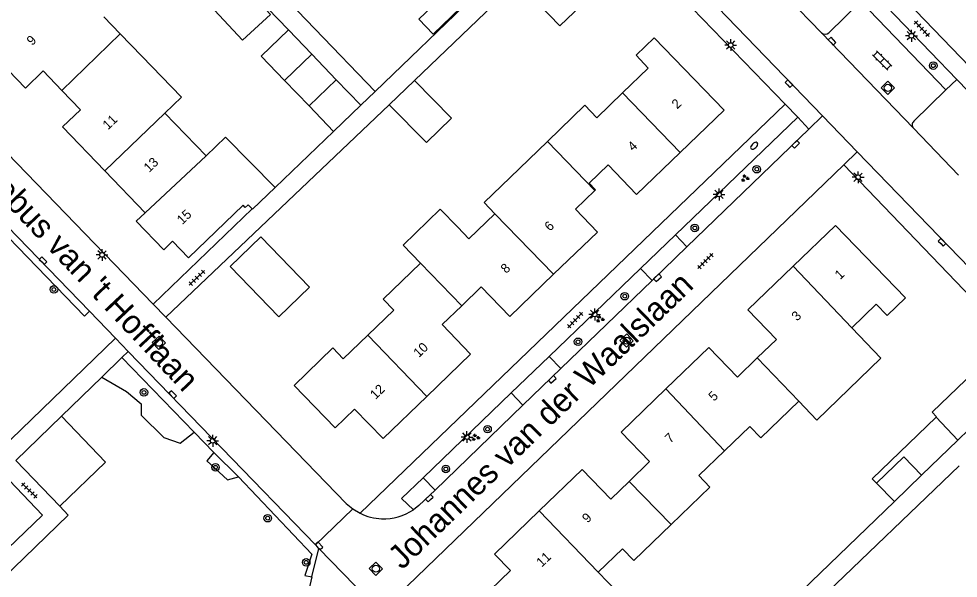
# Model space of a CAD drawing. Extents: x 137999 to 141000, y 397500 to 400501.
# Drawn here: x 138533.8 to 138633.1, y 399346.9 to 399406.1 of the extents above; entities that cross this region are included whole.
import ezdxf

# ---------------------------------------------------------------- set-up
doc = ezdxf.new("R2010")
doc.units = 0
for name, color, linetype in [('gg-afsc-erfafscheiding', 7, 'Continuous'), ('gg-anno-huisnummerreeks BGT', 7, 'Continuous'), ('gg-anno-openbare ruimte label', 7, 'Continuous'), ('gg-bbg-bijgebouw', 7, 'Continuous'), ('gg-bbg-gedigitaliseerde bebouwing', 7, 'Continuous'), ('gg-bbg-gedigitaliseerde bijgebouw', 7, 'Continuous'), ('gg-bbg-hoofdgebouw', 7, 'Continuous'), ('gg-bbg-luifel en loopbrug', 7, 'Continuous'), ('gg-bbg-tussenscheiding', 7, 'Continuous'), ('gg-knt-verharding', 7, 'Continuous'), ('gg-knt-verharding nz', 7, 'Continuous'), ('gt-grn-groengrens', 7, 'Continuous'), ('gt-grn-weggrens', 7, 'Continuous'), ('gt-symb-boom', 7, 'Continuous'), ('gt-symb-brandkraan', 7, 'Continuous'), ('gt-symb-groenvak', 7, 'Continuous'), ('gt-symb-klinker verharding', 7, 'Continuous'), ('gt-symb-kolk', 7, 'Continuous'), ('gt-symb-lichtmast', 7, 'Continuous'), ('gt-symb-rioolschacht', 7, 'Continuous'), ('gt-symb-tegel verharding', 7, 'Continuous')]:
    doc.layers.add(name, color=color, linetype=linetype)

# ---------------------------------------------------------------- blocks, each defined once
blk = doc.blocks.new('gt0-BOOM')
at = {"layer": 'gt-symb-boom'}
for radius in [0.4, 0.2]:
    blk.add_circle((0, 0), radius, dxfattribs=at)
blk = doc.blocks.new('gt0-KOLK')
at = {"layer": 'gt-symb-kolk'}
blk.add_lwpolyline([(0, 0), (0.375, 0), (0.375, 0.4), (-0.375, 0.4), (-0.375, 0), (0, 0)], dxfattribs=at)
blk = doc.blocks.new('gt0-LMAST')
at = {"layer": 'gt-symb-lichtmast'}
for p, q in [((-0.182, 0.173), (-0.447, 0.438)), ((-0.005, 0.246), (-0.005, 0.621)), ((0.172, 0.173), (0.437, 0.438)), ((-0.255, -0.004), (-0.63, -0.004)), ((-0.182, -0.181), (-0.447, -0.446)), ((-0.005, -0.254), (-0.005, -0.629)), ((0.437, -0.446), (0.172, -0.181)), ((0.245, -0.004), (0.62, -0.004))]:
    blk.add_line(p, q, dxfattribs=at)
blk.add_circle((-0.005, -0.004), 0.25, dxfattribs=at)
blk = doc.blocks.new('gt0-RS')
at = {"layer": 'gt-symb-rioolschacht'}
blk.add_lwpolyline([(-0.5, -0.5), (0.5, -0.5), (0.5, 0.5), (-0.5, 0.5)], close=True, dxfattribs=at)
blk.add_circle((0, 0), 0.375, dxfattribs=at)
blk = doc.blocks.new('gt0-TEG1')
at = {"layer": 'gt-symb-tegel verharding'}
for p, q in [((-1.125, 0), (1.125, 0)), ((-0.9, -0.25), (-0.9, 0.25)), ((-0.45, -0.25), (-0.45, 0.25)), ((0, -0.25), (0, 0.25)), ((0.45, -0.25), (0.45, 0.25)), ((0.9, -0.25), (0.9, 0.25))]:
    blk.add_line(p, q, dxfattribs=at)
blk = doc.blocks.new('gt0-KL1')
at = {"layer": 'gt-symb-klinker verharding'}
for p, q in [((-1.15, 0.3), (1.15, 0.3)), ((-1, -0.3), (-1, 0.3)), ((-0.5, 0.3), (-0.5, 0.45)), ((0, -0.3), (0, 0.3)), ((0.5, 0.3), (0.5, 0.45)), ((1, -0.3), (1, 0.3)), ((-1.15, -0.3), (1.15, -0.3)), ((-0.5, -0.45), (-0.5, -0.3)), ((0.5, -0.45), (0.5, -0.3))]:
    blk.add_line(p, q, dxfattribs=at)
blk = doc.blocks.new('gt0-GRVAK')
at = {"layer": 'gt-symb-groenvak'}
for p, q in [((-0.11, 0.189), (-0.228, 0.24)), ((-0.182, 0.153), (0.088, 0.153)), ((-0.091, 0.211), (-0.156, 0.322)), ((-0.047, 0.214), (-0.047, 0.393)), ((-0.004, 0.211), (0.061, 0.322)), ((0.015, 0.189), (0.133, 0.24)), ((0.262, -0.052), (0.197, 0.059)), ((0.305, -0.049), (0.305, 0.13)), ((0.349, -0.052), (0.414, 0.059)), ((-0.245, -0.228), (-0.363, -0.177)), ((-0.318, -0.264), (-0.047, -0.264)), ((-0.226, -0.206), (-0.291, -0.095)), ((-0.183, -0.203), (-0.183, -0.024)), ((-0.139, -0.206), (-0.074, -0.095)), ((-0.12, -0.228), (-0.002, -0.177)), ((0.243, -0.074), (0.125, -0.023)), ((0.17, -0.11), (0.441, -0.11)), ((0.368, -0.074), (0.486, -0.023))]:
    blk.add_line(p, q, dxfattribs=at)
blk = doc.blocks.new('gt0-BR')
at = {"layer": 'gt-symb-brandkraan'}
for centre, radius, start, end in [((-0.244, 0), 0.206, 107.56694, 252.43307), ((0.599, -2.664), 3, 106.89205, 107.56694), ((0, -0.691), 0.938, 73.10799, 106.89205), ((-0.599, -2.664), 3, 72.43309, 73.10799), ((0.244, 0), 0.206, 287.56695, 72.43309), ((0.599, 2.664), 3, 252.43307, 253.10797), ((0, 0.691), 0.938, 253.10797, 286.89206), ((-0.599, 2.664), 3, 286.89206, 287.56695)]:
    blk.add_arc(centre, radius, start, end, dxfattribs=at)

msp = doc.modelspace()

# ---------------------------------------------------------------- linework, layer by layer
at = {"layer": 'gg-afsc-erfafscheiding'}
for p, q in [((138562.298, 399404.947), (138532.585, 399435.849)), ((138586.503, 399410.042), (138575.628, 399399.609)), ((138571.465, 399398.456), (138569.945, 399396.994)), ((138572.963, 399397.042), (138549.319, 399374.578)), ((138560.882, 399388.271), (138567.063, 399394.22)), ((138615.788, 399342.104), (138633.204, 399358.84)), ((138594.27, 399324.093), (138626.367, 399355.056))]:
    msp.add_line(p, q, dxfattribs=at)
msp.add_lwpolyline([(138571.465, 399398.456), (138526.794, 399444.89), (138537.203, 399454.925)], dxfattribs=at)
at = {"layer": 'gg-bbg-bijgebouw'}
for p, q in [((138637.561, 399365.896), (138633.07, 399361.547)), ((138629.241, 399357.839), (138626.367, 399355.056))]:
    msp.add_line(p, q, dxfattribs=at)
msp.add_lwpolyline([(138586.503, 399410.042), (138591, 399405.377), (138596.246, 399410.424), (138591.726, 399415.077)], dxfattribs=at)
at = {"layer": 'gg-bbg-gedigitaliseerde bebouwing'}
for p, q in [((138542.792, 399406.337), (138544.514, 399404.551)), ((138546.806, 399402.175), (138544.514, 399404.551)), ((138549.245, 399396.149), (138553.598, 399391.637)), ((138589.692, 399393.158), (138585.75, 399389.352)), ((138597.104, 399345.478), (138595.056, 399347.598))]:
    msp.add_line(p, q, dxfattribs=at)
for points in [[(138546.806, 399402.175), (138550.993, 399397.835), (138549.245, 399396.149)], [(138599.05, 399402.27), (138600.34, 399400.902), (138597.634, 399398.289)], [(138597.634, 399398.289), (138594.918, 399395.667), (138593.651, 399396.979), (138589.692, 399393.158)], [(138553.598, 399391.637), (138555.65, 399393.597), (138560.882, 399388.271)], [(138585.75, 399389.352), (138582.988, 399386.686), (138584.132, 399385.501)], [(138580.197, 399384.087), (138578.349, 399385.998), (138574.413, 399382.191), (138576.258, 399380.284)], [(138584.132, 399385.501), (138581.389, 399382.852), (138580.197, 399384.087)], [(138576.258, 399380.284), (138572.312, 399376.475), (138573.441, 399375.305), (138570.686, 399372.645)], [(138625.6, 399374.73), (138624.454, 399375.921), (138621.853, 399373.418)], [(138621.853, 399373.418), (138624.948, 399370.222), (138618.177, 399363.665), (138616.248, 399365.657)], [(138570.686, 399372.645), (138568.101, 399370.15), (138566.989, 399371.302), (138562.89, 399367.34)], [(138616.248, 399365.657), (138612.248, 399361.808), (138611.093, 399363.007), (138608.42, 399360.434)], [(138608.42, 399360.434), (138605.678, 399357.796), (138606.855, 399356.572), (138602.757, 399352.629)], [(138602.757, 399352.629), (138598.802, 399348.823), (138597.613, 399350.059), (138595.056, 399347.598)]]:
    msp.add_lwpolyline(points, dxfattribs=at)
at = {"layer": 'gg-bbg-gedigitaliseerde bijgebouw'}
for p, q in [((138562.298, 399404.947), (138564.768, 399402.379)), ((138564.768, 399402.379), (138567.357, 399399.687)), ((138564.473, 399396.912), (138561.882, 399399.603)), ((138564.473, 399396.912), (138567.357, 399399.687)), ((138575.628, 399399.609), (138572.963, 399397.042)), ((138633.07, 399361.547), (138630.772, 399363.98)), ((138624.49, 399356.997), (138626.367, 399355.056))]:
    msp.add_line(p, q, dxfattribs=at)
for points in [[(138577.609, 399404.512), (138576.077, 399406.101), (138578.996, 399408.916), (138580.528, 399407.326), (138577.609, 399404.512)], [(138561.882, 399399.603), (138559.412, 399402.169), (138562.298, 399404.947)], [(138572.963, 399397.042), (138576.883, 399393.042), (138579.526, 399395.632), (138575.628, 399399.609)], [(138556.144, 399379.926), (138559.376, 399383.052), (138564.522, 399377.732), (138561.29, 399374.606), (138556.144, 399379.926)], [(138634.808, 399368.789), (138630.372, 399364.5), (138630.825, 399364.031), (138630.772, 399363.98)], [(138629.241, 399357.839), (138627.362, 399359.778), (138624.49, 399356.997)]]:
    msp.add_lwpolyline(points, dxfattribs=at)
at = {"layer": 'gg-bbg-hoofdgebouw'}
for p, q in [((138599.1, 399387.54), (138603.719, 399391.984)), ((138542.874, 399390.051), (138547.142, 399385.616)), ((138551.73, 399380.85), (138557.497, 399386.4)), ((138558.046, 399386.458), (138558.465, 399386.023)), ((138590.327, 399379.097), (138594.96, 399383.57)), ((138550.051, 399382.595), (138551.73, 399380.85)), ((138585.763, 399347.766), (138579.681, 399341.886))]:
    msp.add_line(p, q, dxfattribs=at)
for points in [[(138603.719, 399391.984), (138608.36, 399396.45), (138600.98, 399404.13), (138599.05, 399402.27)], [(138529.99, 399403.445), (138534.48, 399398.79), (138536.37, 399400.62), (138538.344, 399398.555)], [(138542.874, 399390.051), (138538.4, 399394.7), (138540.3, 399396.51), (138538.344, 399398.555)], [(138599.1, 399387.54), (138596.093, 399390.676), (138594.092, 399388.757), (138594.778, 399388.041), (138594.707, 399387.973)], [(138560.882, 399388.271), (138558.504, 399385.983), (138558.465, 399386.023)], [(138594.707, 399387.973), (138592.639, 399385.99), (138594.96, 399383.57)], [(138558.046, 399386.458), (138557.732, 399386.156), (138557.497, 399386.4)], [(138547.142, 399385.616), (138546.21, 399384.719), (138549.113, 399381.692), (138550.051, 399382.595)], [(138615.679, 399379.953), (138620.15, 399384.26), (138627.54, 399376.61), (138625.6, 399374.73)], [(138611.871, 399370.25), (138613.89, 399372.2), (138610.88, 399375.33), (138615.679, 399379.953)], [(138580.628, 399375.777), (138582.69, 399377.76), (138585.7, 399374.63), (138590.327, 399379.097)], [(138576.933, 399366.183), (138581.56, 399370.65), (138578.55, 399373.78), (138580.628, 399375.777)], [(138602.219, 399366.97), (138606.76, 399371.34), (138609.77, 399368.22), (138611.871, 399370.25)], [(138562.89, 399367.34), (138567.23, 399362.85), (138569.28, 399364.83), (138572.3, 399361.71), (138576.933, 399366.183)], [(138598.31, 399357.179), (138600.49, 399359.28), (138597.48, 399362.41), (138602.219, 399366.97)], [(138588.821, 399354.058), (138593.37, 399358.44), (138596.38, 399355.32), (138598.31, 399357.179)], [(138585.763, 399347.766), (138584.09, 399349.5), (138588.821, 399354.058)]]:
    msp.add_lwpolyline(points, dxfattribs=at)
at = {"layer": 'gg-bbg-luifel en loopbrug'}
for p, q in [((138567.357, 399399.687), (138569.945, 399396.994)), ((138569.945, 399396.994), (138567.063, 399394.22)), ((138567.063, 399394.22), (138564.473, 399396.912)), ((138633.07, 399361.547), (138629.241, 399357.839))]:
    msp.add_line(p, q, dxfattribs=at)
for points in [[(138551.263, 399411.068), (138551, 399410.825), (138557.446, 399403.854), (138560.406, 399406.592), (138555.684, 399411.699)], [(138630.772, 399363.98), (138624.036, 399357.467), (138624.49, 399356.997)]]:
    msp.add_lwpolyline(points, dxfattribs=at)
at = {"layer": 'gg-bbg-tussenscheiding'}
for p, q in [((138544.514, 399404.551), (138538.344, 399398.555)), ((138564.768, 399402.379), (138561.882, 399399.603)), ((138603.719, 399391.984), (138597.634, 399398.289)), ((138549.245, 399396.149), (138542.874, 399390.051)), ((138594.707, 399387.973), (138589.692, 399393.158)), ((138547.142, 399385.616), (138553.598, 399391.637)), ((138590.327, 399379.097), (138584.132, 399385.501)), ((138580.628, 399375.777), (138576.258, 399380.284)), ((138615.679, 399379.953), (138621.853, 399373.418)), ((138576.933, 399366.183), (138570.686, 399372.645)), ((138616.248, 399365.657), (138611.871, 399370.25)), ((138602.219, 399366.97), (138608.42, 399360.434)), ((138602.757, 399352.629), (138598.31, 399357.179)), ((138588.821, 399354.058), (138595.056, 399347.598))]:
    msp.add_line(p, q, dxfattribs=at)
at = {"layer": 'gg-knt-verharding'}
for p, q in [((138531.226, 399486.574), (138618.77, 399395.87)), ((138503.24, 399422.202), (138548.006, 399375.941)), ((138571.465, 399398.456), (138593.253, 399419.425)), ((138614.83, 399397.11), (138594.734, 399417.888)), ((138614.467, 399408.99), (138618.663, 399404.64)), ((138632.984, 399399.715), (138623.96, 399409.087)), ((138622.835, 399407.952), (138619.421, 399404.661)), ((138622.835, 399407.952), (138631.824, 399398.61)), ((138618.663, 399404.64), (138628.387, 399394.556)), ((138631.824, 399398.61), (138632.984, 399399.715)), ((138631.824, 399398.61), (138628.419, 399395.285)), ((138569.886, 399353.814), (138614.83, 399397.11)), ((138603.222, 399383.256), (138616.144, 399395.708)), ((138616.144, 399395.708), (138617.323, 399394.471)), ((138618.77, 399395.87), (138617.323, 399394.471)), ((138622.45, 399392.05), (138618.77, 399395.87)), ((138522.628, 399394.451), (138541.267, 399375.185)), ((138617.323, 399394.471), (138604.417, 399381.999)), ((138628.387, 399394.556), (138633.164, 399389.603)), ((138622.45, 399392.05), (138621.021, 399390.671)), ((138622.45, 399392.05), (138662.293, 399350.768)), ((138573.864, 399345.159), (138621.021, 399390.671)), ((138641.4, 399369.436), (138621.021, 399390.671)), ((138558.465, 399386.023), (138548.006, 399375.941)), ((138604.417, 399381.999), (138603.222, 399383.256)), ((138604.417, 399381.999), (138600.746, 399378.451)), ((138589.875, 399370.406), (138599.513, 399379.722)), ((138599.513, 399379.722), (138600.746, 399378.451)), ((138600.746, 399378.451), (138591.089, 399369.117)), ((138541.267, 399375.185), (138544.013, 399372.347)), ((138544.691, 399370.291), (138542.556, 399368.225)), ((138545.367, 399370.946), (138544.691, 399370.291)), ((138545.367, 399370.946), (138565.165, 399350.46)), ((138591.089, 399369.117), (138589.875, 399370.406)), ((138538.289, 399364.096), (138542.556, 399368.225)), ((138591.089, 399369.117), (138587.083, 399365.245)), ((138576.54, 399357.562), (138585.833, 399366.549)), ((138585.833, 399366.549), (138587.083, 399365.245)), ((138587.083, 399365.245), (138577.8, 399356.274)), ((138577.8, 399356.274), (138576.54, 399357.562)), ((138574.264, 399355.392), (138575.525, 399354.19)), ((138569.106, 399354.277), (138569.886, 399353.814)), ((138564.783, 399347.079), (138565.528, 399350.084)), ((138564.783, 399347.079), (138564.039, 399343.986))]:
    msp.add_line(p, q, dxfattribs=at)
for points in [[(138611.48, 399424.83), (138651.46, 399383.27), (138647.96, 399379.83), (138669.327, 399357.498)], [(138549.319, 399374.578), (138568.41, 399354.86), (138569.106, 399354.277)], [(138524.358, 399342.143), (138536.295, 399353.616), (138530.685, 399359.465), (138544.013, 399372.347)], [(138538.131, 399354.56), (138533.477, 399359.409), (138538.289, 399364.096)], [(138538.289, 399364.096), (138542.951, 399359.237), (138538.131, 399354.56)], [(138577.8, 399356.274), (138576.097, 399354.628), (138575.525, 399354.19)], [(138538.131, 399354.56), (138539.024, 399353.603), (138526.277, 399341.287)]]:
    msp.add_lwpolyline(points, dxfattribs=at)
for centre, radius, start, end in [((138619.031, 399405.042), 0.545, 227.49155, 315.68234), ((138628.764, 399394.905), 0.513, 132.19105, 222.7821), ((138572.373, 399358.872), 5.636, 243.81904, 267.77584), ((138572.384, 399358.881), 5.646, 267.66995, 303.80737)]:
    msp.add_arc(centre, radius, start, end, dxfattribs=at)
at = {"layer": 'gg-knt-verharding nz'}
for p, q in [((138637.942, 399394.567), (138632.984, 399399.715)), ((138599.513, 399379.722), (138603.222, 399383.256)), ((138544.013, 399372.347), (138545.367, 399370.946)), ((138585.833, 399366.549), (138589.875, 399370.406)), ((138574.264, 399355.392), (138576.54, 399357.562))]:
    msp.add_line(p, q, dxfattribs=at)
at = {"layer": 'gt-grn-groengrens'}
for p, q in [((138552.339, 399362.387), (138544.691, 399370.291)), ((138552.339, 399362.387), (138554.403, 399360.258)), ((138554.403, 399360.258), (138557.01, 399357.683))]:
    msp.add_line(p, q, dxfattribs=at)
for points in [[(138520.904, 399392.783), (138521.427, 399392.242), (138522.604, 399393.38), (138540.746, 399374.681), (138541.267, 399375.185)], [(138542.556, 399368.225), (138545.188, 399366.703), (138546.711, 399365.376), (138546.73, 399364.178), (138549.123, 399361.822), (138550.867, 399361.227), (138552.339, 399362.387)], [(138554.403, 399360.258), (138553.666, 399359.351), (138555.852, 399357.341), (138557.01, 399357.683)], [(138557.01, 399357.683), (138564.761, 399349.49), (138564.016, 399347.212), (138564.783, 399347.079)]]:
    msp.add_lwpolyline(points, dxfattribs=at)
at = {"layer": 'gt-grn-weggrens'}
for p, q in [((138616.144, 399395.708), (138614.83, 399397.11)), ((138548.006, 399375.941), (138549.319, 399374.578)), ((138569.106, 399354.277), (138565.165, 399350.46)), ((138565.528, 399350.084), (138565.165, 399350.46)), ((138570.575, 399344.865), (138565.528, 399350.084))]:
    msp.add_line(p, q, dxfattribs=at)

# ---------------------------------------------------------------- block references
at = {"layer": 'gt-symb-boom'}
for p in [(138630.482, 399401.177), (138611.816, 399390.218), (138605.265, 399384), (138537.501, 399377.493), (138597.858, 399376.782), (138592.918, 399371.956), (138547.022, 399366.601), (138583.35, 399362.713), (138554.585, 399358.676), (138578.94, 399358.504), (138560.104, 399353.293), (138564.175, 399348.62)]:
    msp.add_blockref('gt0-BOOM', p, dxfattribs=at)
at = {"layer": 'gt-symb-brandkraan', "rotation": 43.946589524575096}
msp.add_blockref('gt0-BR', (138611.549, 399392.7), dxfattribs=at)
at = {"layer": 'gt-symb-groenvak'}
for p in [(138610.572, 399389.264), (138595.241, 399374.361), (138582.069, 399361.833)]:
    msp.add_blockref('gt0-GRVAK', p, dxfattribs=at)
at = {"layer": 'gt-symb-klinker verharding', "rotation": -45.000000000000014}
msp.add_blockref('gt0-KL1', (138625.073, 399401.722), dxfattribs=at)
at = {"layer": 'gt-symb-kolk'}
for p, rotation in [((138619.639, 399403.624), -46.05341047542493), ((138615.066, 399399.129), -46.05341047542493), ((138616.06, 399392.698), 44.02760489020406), ((138631.267, 399382.339), -46.05341047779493), ((138536.213, 399380.404), -45.972395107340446), ((138601.458, 399378.584), 44.02760489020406), ((138590.328, 399367.825), 44.02760489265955), ((138549.908, 399366.234), -45.972395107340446), ((138577.334, 399355.267), 44.02760489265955), ((138565.383, 399350.234), -45.972395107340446)]:
    msp.add_blockref('gt0-KOLK', p, dxfattribs=dict(at, rotation=rotation))
at = {"layer": 'gt-symb-lichtmast'}
for p in [(138628.179, 399404.338), (138609.069, 399403.355), (138622.54, 399389.366), (138607.834, 399387.551), (138542.599, 399381.149), (138594.688, 399374.856), (138581.18, 399361.881), (138554.299, 399361.485)]:
    msp.add_blockref('gt0-LMAST', p, dxfattribs=at)
at = {"layer": 'gt-symb-rioolschacht'}
for p, rotation in [((138625.677, 399398.824), -46.05341047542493), ((138548.603, 399371.857), 44.02760489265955), ((138598.058, 399372.08), 44.02760489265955), ((138571.541, 399347.946), 44.02760489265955)]:
    msp.add_blockref('gt0-RS', p, dxfattribs=dict(at, rotation=rotation))
at = {"layer": 'gt-symb-tegel verharding'}
for p, rotation in [((138629.274, 399405.073), 133.01389341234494), ((138606.386, 399380.491), 45.0000000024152), ((138552.622, 399378.731), 43.946589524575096), ((138592.615, 399374.258), 45.972395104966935), ((138534.904, 399356.231), -44.10862414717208)]:
    msp.add_blockref('gt0-TEG1', p, dxfattribs=dict(at, rotation=rotation))

# ---------------------------------------------------------------- texts
at = {"layer": 'gg-anno-huisnummerreeks BGT'}
for s, rotation, p in [('9', 43.9, (138535.197, 399403.249)), ('2', 43.9, (138603.397, 399396.533)), ('11', 43.9, (138543.225, 399394.333)), ('4', 43.9, (138598.745, 399392.056)), ('13', 43.9, (138547.569, 399389.82)), ('15', 43.8, (138551.075, 399384.302)), ('6', 44, (138589.95, 399383.597)), ('8', 44, (138585.32, 399379.127)), ('1', 43.9, (138620.638, 399378.482)), ('3', 43.9, (138616.079, 399374.091)), ('10', 44, (138576.087, 399370.23)), ('12', 44, (138571.507, 399365.808)), ('5', 43.9, (138607.286, 399365.603)), ('7', 43.9, (138602.676, 399361.166)), ('9', 43.9, (138593.922, 399352.724)), ('11', 43.9, (138589.085, 399348.064))]:
    msp.add_text(s, height=1, rotation=rotation, dxfattribs=at).set_placement(p)
at = {"layer": 'gg-anno-openbare ruimte label'}
for s, rotation, p in [("Jacobus van 't Hofflaan", 313.3, (138527.469, 399391.725)), ('Johannes van der Waalslaan', 44.1, (138574.314, 399347.762))]:
    msp.add_text(s, height=2.5, rotation=rotation, dxfattribs=at).set_placement(p)

doc.saveas('drawing.dxf')
